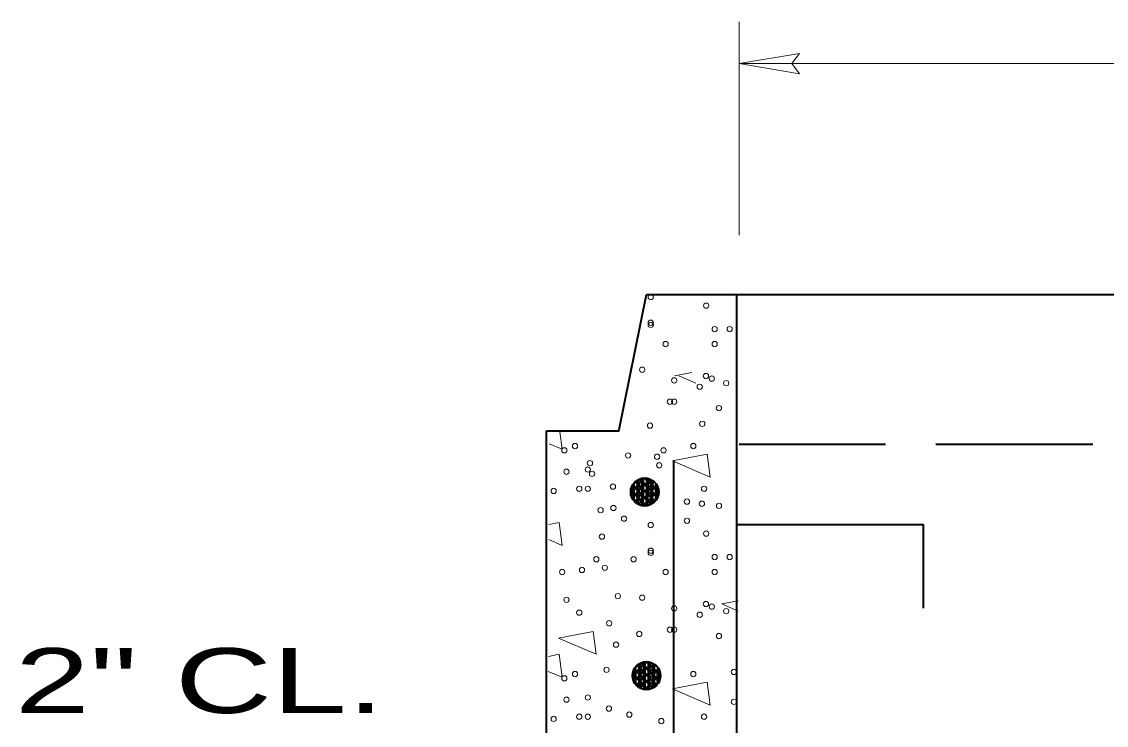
# Model space of a CAD drawing. Extents: x 5.1 to 20.2, y -16.7 to 4.3.
# Drawn here: x 9.029 to 11.185, y -3.824 to -2.427 of the extents above; entities that cross this region are included whole.
import ezdxf
from ezdxf.enums import TextEntityAlignment as Align

# ---------------------------------------------------------------- set-up
doc = ezdxf.new("R2010")
doc.units = 0
doc.header["$LTSCALE"] = 0.052
doc.linetypes.add('LONG_DASHED', pattern=[7.5, 6, -1.5])
for name, color, linetype, lineweight in [('1', 7, 'Continuous', 35), ('10', 7, 'Continuous', 13), ('13', 7, 'Continuous', 25), ('6', 7, 'Continuous', 13)]:
    doc.layers.add(name, color=color, linetype=linetype, lineweight=lineweight)

msp = doc.modelspace()

# ---------------------------------------------------------------- linework, layer by layer
at = {"layer": '1'}
for p, q in [((10.21608, -3.23967), (10.27058, -2.96833)), ((10.27058, -2.96833), (13.67525, -2.96833)), ((10.45017, -4.44358), (10.45017, -2.96833)), ((10.07242, -3.23933), (10.21608, -3.23933)), ((10.07242, -4.73767), (10.07242, -3.23933)), ((10.32492, -4.35042), (10.32492, -3.298)), ((10.26408, -3.3365), (10.24317, -3.35725)), ((10.267, -3.35925), (10.24817, -3.34033)), ((10.26058, -3.35275), (10.24817, -3.34033)), ((10.25408, -3.34617), (10.24817, -3.34033)), ((10.26775, -3.35825), (10.24908, -3.33958)), ((10.26125, -3.35175), (10.24908, -3.33958)), ((10.25475, -3.34517), (10.24908, -3.33958)), ((10.26775, -3.33292), (10.24958, -3.35075)), ((10.25275, -3.35983), (10.25283, -3.33692)), ((10.25275, -3.35067), (10.25283, -3.33692)), ((10.25275, -3.36908), (10.25283, -3.3395)), ((10.25283, -3.34142), (10.25283, -3.33692)), ((10.25533, -3.35983), (10.25542, -3.33542)), ((10.25533, -3.36908), (10.25542, -3.3395)), ((10.25542, -3.35067), (10.25542, -3.33542)), ((10.25542, -3.34142), (10.25542, -3.33542)), ((10.27358, -3.35275), (10.25608, -3.33525)), ((10.26708, -3.34625), (10.25608, -3.33525)), ((10.26067, -3.33967), (10.25608, -3.33525)), ((10.26775, -3.33292), (10.25617, -3.34425)), ((10.27717, -3.3365), (10.25617, -3.35733)), ((10.27425, -3.35175), (10.25725, -3.33467)), ((10.26775, -3.34525), (10.25725, -3.33467)), ((10.26125, -3.33875), (10.25725, -3.33467)), ((10.28008, -3.35933), (10.25925, -3.33842)), ((10.28075, -3.35833), (10.25992, -3.33742)), ((10.26192, -3.35992), (10.262, -3.33333)), ((10.26192, -3.36908), (10.262, -3.3395)), ((10.262, -3.35067), (10.262, -3.33333)), ((10.262, -3.3415), (10.262, -3.33333)), ((10.2785, -3.33525), (10.26267, -3.35083)), ((10.2645, -3.36908), (10.26467, -3.33958)), ((10.26458, -3.35992), (10.26467, -3.33292)), ((10.26458, -3.35067), (10.26467, -3.33292)), ((10.26458, -3.3415), (10.26467, -3.33292)), ((10.28658, -3.35283), (10.26683, -3.33292)), ((10.28008, -3.34625), (10.26683, -3.33292)), ((10.27358, -3.33975), (10.26683, -3.33292)), ((10.26708, -3.33317), (10.26683, -3.33292)), ((10.28733, -3.35183), (10.26842, -3.33292)), ((10.28083, -3.34525), (10.26842, -3.33292)), ((10.27433, -3.33883), (10.26842, -3.33292)), ((10.28625, -3.34042), (10.26917, -3.35733)), ((10.27117, -3.35992), (10.27125, -3.33317)), ((10.27117, -3.35067), (10.27125, -3.33317)), ((10.27117, -3.36908), (10.27125, -3.33958)), ((10.27125, -3.3415), (10.27125, -3.33317)), ((10.29308, -3.35933), (10.27233, -3.33842)), ((10.29375, -3.35833), (10.27292, -3.33742)), ((10.27375, -3.35992), (10.27383, -3.33367)), ((10.27375, -3.36917), (10.27383, -3.33958)), ((10.27383, -3.35067), (10.27383, -3.33367)), ((10.27383, -3.3415), (10.27383, -3.33367)), ((10.28033, -3.36917), (10.28042, -3.33958)), ((10.28042, -3.35992), (10.28042, -3.33625)), ((10.28042, -3.35075), (10.28042, -3.33625)), ((10.28042, -3.3415), (10.28042, -3.33625)), ((10.283, -3.35992), (10.28308, -3.33775)), ((10.283, -3.35075), (10.28308, -3.33775)), ((10.283, -3.36917), (10.28308, -3.33958)), ((10.28308, -3.3415), (10.28308, -3.33775)), ((10.25758, -3.343), (10.2395, -3.361)), ((10.251, -3.3495), (10.2395, -3.361)), ((10.2445, -3.35592), (10.2395, -3.361)), ((10.2605, -3.37875), (10.23958, -3.35783)), ((10.254, -3.37233), (10.23958, -3.35783)), ((10.2475, -3.36575), (10.23958, -3.35783)), ((10.241, -3.35917), (10.23958, -3.35783)), ((10.25467, -3.37133), (10.23975, -3.35625)), ((10.24808, -3.36475), (10.23975, -3.35625)), ((10.24167, -3.35817), (10.23975, -3.35625)), ((10.26117, -3.37783), (10.24033, -3.35692)), ((10.2575, -3.35592), (10.24175, -3.37175)), ((10.26058, -3.36575), (10.24267, -3.34775)), ((10.25408, -3.35925), (10.24267, -3.34775)), ((10.24758, -3.35267), (10.24267, -3.34775)), ((10.26408, -3.3495), (10.24308, -3.37033)), ((10.26117, -3.36483), (10.24317, -3.34667)), ((10.25467, -3.35825), (10.24317, -3.34667)), ((10.24817, -3.35167), (10.24317, -3.34667)), ((10.2435, -3.369), (10.24358, -3.34608)), ((10.2435, -3.35983), (10.24358, -3.34608)), ((10.2435, -3.37508), (10.24358, -3.34867)), ((10.2435, -3.37508), (10.2435, -3.35792)), ((10.24358, -3.35058), (10.24358, -3.34608)), ((10.24608, -3.36908), (10.24617, -3.3425)), ((10.24608, -3.37825), (10.24617, -3.34867)), ((10.24608, -3.37875), (10.24617, -3.35792)), ((10.24617, -3.35983), (10.24617, -3.3425)), ((10.24617, -3.35058), (10.24617, -3.3425)), ((10.267, -3.37233), (10.24617, -3.35133)), ((10.26767, -3.37133), (10.24683, -3.35042)), ((10.27058, -3.343), (10.24958, -3.36383)), ((10.27058, -3.356), (10.24958, -3.37692)), ((10.25267, -3.37825), (10.25275, -3.34875)), ((10.2735, -3.37883), (10.25267, -3.35783)), ((10.25267, -3.38433), (10.25275, -3.35792)), ((10.2735, -3.36583), (10.25275, -3.34492)), ((10.27417, -3.37792), (10.25333, -3.35692)), ((10.27425, -3.36483), (10.25342, -3.34392)), ((10.25525, -3.38583), (10.25533, -3.35792)), ((10.25533, -3.37825), (10.25542, -3.34875)), ((10.27708, -3.34958), (10.25608, -3.37042)), ((10.28, -3.37233), (10.25925, -3.35133)), ((10.28075, -3.37142), (10.25983, -3.35042)), ((10.26183, -3.3875), (10.262, -3.358)), ((10.26192, -3.37833), (10.262, -3.34875)), ((10.2835, -3.356), (10.26258, -3.37692)), ((10.28358, -3.34308), (10.26267, -3.36392)), ((10.2645, -3.37833), (10.26458, -3.34875)), ((10.2645, -3.3875), (10.26458, -3.358)), ((10.28658, -3.36583), (10.26575, -3.34492)), ((10.2865, -3.37883), (10.26575, -3.35792)), ((10.28725, -3.37792), (10.26633, -3.357)), ((10.28725, -3.36483), (10.26642, -3.34392)), ((10.29008, -3.34958), (10.26917, -3.37042)), ((10.27108, -3.37833), (10.27117, -3.34875)), ((10.27108, -3.38758), (10.27117, -3.358)), ((10.29267, -3.372), (10.27225, -3.35142)), ((10.29317, -3.37083), (10.27292, -3.3505)), ((10.27367, -3.38758), (10.27375, -3.358)), ((10.27375, -3.37833), (10.27383, -3.34875)), ((10.29192, -3.34775), (10.27567, -3.36392)), ((10.29492, -3.35775), (10.27567, -3.377)), ((10.29267, -3.372), (10.27867, -3.35792)), ((10.295, -3.36125), (10.27875, -3.345)), ((10.295, -3.35967), (10.27942, -3.344)), ((10.29317, -3.37083), (10.27942, -3.357)), ((10.28033, -3.37833), (10.28042, -3.34883)), ((10.28033, -3.38525), (10.28042, -3.358)), ((10.29492, -3.35775), (10.28217, -3.3705)), ((10.28292, -3.37833), (10.283, -3.34883)), ((10.28292, -3.38367), (10.283, -3.358)), ((10.295, -3.36125), (10.28525, -3.35142)), ((10.295, -3.35967), (10.28592, -3.3505)), ((10.2895, -3.37733), (10.28958, -3.34883)), ((10.2895, -3.37733), (10.28958, -3.35808)), ((10.28958, -3.36917), (10.28967, -3.34417)), ((10.28958, -3.36), (10.28967, -3.34417)), ((10.28958, -3.35075), (10.28967, -3.34417)), ((10.29217, -3.36917), (10.29225, -3.34842)), ((10.29217, -3.36), (10.29225, -3.34842)), ((10.29217, -3.37317), (10.29225, -3.34883)), ((10.29217, -3.37317), (10.29217, -3.35808)), ((10.29225, -3.35075), (10.29225, -3.34842)), ((10.25675, -3.38642), (10.24142, -3.371)), ((10.25458, -3.38433), (10.24142, -3.371)), ((10.24808, -3.37783), (10.24142, -3.371)), ((10.24167, -3.37125), (10.24142, -3.371)), ((10.251, -3.3625), (10.24175, -3.37175)), ((10.24442, -3.369), (10.24175, -3.37175)), ((10.25367, -3.385), (10.24283, -3.37408)), ((10.25367, -3.385), (10.24283, -3.37408)), ((10.2475, -3.37875), (10.24283, -3.37408)), ((10.2435, -3.37508), (10.2435, -3.36708)), ((10.24608, -3.37875), (10.24608, -3.36717)), ((10.25367, -3.385), (10.24608, -3.37742)), ((10.26692, -3.38533), (10.24617, -3.36433)), ((10.25675, -3.38642), (10.24675, -3.37642)), ((10.264, -3.3625), (10.24683, -3.37958)), ((10.26767, -3.38442), (10.24683, -3.36333)), ((10.2575, -3.369), (10.24683, -3.37958)), ((10.25092, -3.3755), (10.24683, -3.37958)), ((10.25267, -3.38433), (10.25275, -3.36717)), ((10.27, -3.38842), (10.25267, -3.37092)), ((10.25675, -3.38642), (10.25325, -3.383)), ((10.27142, -3.38817), (10.25333, -3.36992)), ((10.2705, -3.36908), (10.25417, -3.38525)), ((10.264, -3.37558), (10.25417, -3.38525)), ((10.25742, -3.38208), (10.25417, -3.38525)), ((10.25525, -3.38583), (10.25533, -3.36717)), ((10.27708, -3.3625), (10.25608, -3.38342)), ((10.28, -3.38533), (10.25917, -3.36442)), ((10.27, -3.38842), (10.25917, -3.37742)), ((10.27142, -3.38817), (10.25975, -3.37642)), ((10.28067, -3.38442), (10.25983, -3.36342)), ((10.26183, -3.388), (10.26192, -3.36717)), ((10.2835, -3.36908), (10.26417, -3.38833)), ((10.277, -3.37558), (10.26417, -3.38833)), ((10.2705, -3.38208), (10.26417, -3.38833)), ((10.2645, -3.38833), (10.26458, -3.36717)), ((10.28008, -3.38542), (10.26567, -3.37092)), ((10.28108, -3.38483), (10.26633, -3.36992)), ((10.29008, -3.36258), (10.26908, -3.3835)), ((10.27108, -3.38825), (10.27117, -3.36717)), ((10.2875, -3.37983), (10.27225, -3.36442)), ((10.28825, -3.37892), (10.27283, -3.36342)), ((10.27367, -3.38775), (10.27375, -3.36725)), ((10.28033, -3.38525), (10.28033, -3.36725)), ((10.29183, -3.37383), (10.28033, -3.38533)), ((10.29, -3.37567), (10.28033, -3.38533)), ((10.28342, -3.38217), (10.28033, -3.38533)), ((10.29183, -3.37383), (10.28217, -3.3835)), ((10.28292, -3.38367), (10.283, -3.36725)), ((10.29183, -3.37383), (10.28867, -3.377)), ((10.2895, -3.37733), (10.28958, -3.36725)), ((10.29217, -3.37317), (10.29217, -3.36725)), ((10.25367, -3.385), (10.25258, -3.38392)), ((10.2675, -3.70133), (10.24658, -3.72208)), ((10.27042, -3.72408), (10.25158, -3.70517)), ((10.264, -3.71758), (10.25158, -3.70517)), ((10.2575, -3.711), (10.25158, -3.70517)), ((10.27117, -3.72308), (10.2525, -3.70442)), ((10.26467, -3.71658), (10.2525, -3.70442)), ((10.25817, -3.71), (10.2525, -3.70442)), ((10.27117, -3.69775), (10.253, -3.71558)), ((10.25617, -3.72467), (10.25625, -3.70175)), ((10.25617, -3.7155), (10.25625, -3.70175)), ((10.25617, -3.73392), (10.25625, -3.70433)), ((10.25625, -3.70625), (10.25625, -3.70175)), ((10.25875, -3.72467), (10.25883, -3.70025)), ((10.25875, -3.73392), (10.25883, -3.70433)), ((10.25883, -3.7155), (10.25883, -3.70025)), ((10.25883, -3.70625), (10.25883, -3.70025)), ((10.277, -3.71758), (10.2595, -3.70008)), ((10.2705, -3.71108), (10.2595, -3.70008)), ((10.26408, -3.7045), (10.2595, -3.70008)), ((10.27117, -3.69775), (10.25958, -3.70908)), ((10.28058, -3.70133), (10.25958, -3.72217)), ((10.27767, -3.71658), (10.26067, -3.6995)), ((10.27117, -3.71008), (10.26067, -3.6995)), ((10.26467, -3.70358), (10.26067, -3.6995)), ((10.2835, -3.72417), (10.26267, -3.70325)), ((10.28417, -3.72317), (10.26333, -3.70225)), ((10.26533, -3.72475), (10.26542, -3.69817)), ((10.26533, -3.73392), (10.26542, -3.70433)), ((10.26542, -3.7155), (10.26542, -3.69817)), ((10.26542, -3.70633), (10.26542, -3.69817)), ((10.28192, -3.70008), (10.26608, -3.71567)), ((10.26792, -3.73392), (10.26808, -3.70442)), ((10.268, -3.72475), (10.26808, -3.69775)), ((10.268, -3.7155), (10.26808, -3.69775)), ((10.268, -3.70633), (10.26808, -3.69775)), ((10.29, -3.71767), (10.27025, -3.69775)), ((10.2835, -3.71108), (10.27025, -3.69775)), ((10.277, -3.70458), (10.27025, -3.69775)), ((10.2705, -3.698), (10.27025, -3.69775)), ((10.29075, -3.71667), (10.27183, -3.69775)), ((10.28425, -3.71008), (10.27183, -3.69775)), ((10.27775, -3.70367), (10.27183, -3.69775)), ((10.28967, -3.70525), (10.27258, -3.72217)), ((10.27458, -3.72475), (10.27467, -3.698)), ((10.27458, -3.7155), (10.27467, -3.698)), ((10.27458, -3.73392), (10.27467, -3.70442)), ((10.27467, -3.70633), (10.27467, -3.698)), ((10.2965, -3.72417), (10.27575, -3.70325)), ((10.29717, -3.72317), (10.27633, -3.70225)), ((10.27717, -3.72475), (10.27725, -3.6985)), ((10.27717, -3.734), (10.27725, -3.70442)), ((10.27725, -3.7155), (10.27725, -3.6985)), ((10.27725, -3.70633), (10.27725, -3.6985)), ((10.28375, -3.734), (10.28383, -3.70442)), ((10.28383, -3.72475), (10.28383, -3.70108)), ((10.28383, -3.71558), (10.28383, -3.70108)), ((10.28383, -3.70633), (10.28383, -3.70108)), ((10.28642, -3.72475), (10.2865, -3.70258)), ((10.28642, -3.71558), (10.2865, -3.70258)), ((10.28642, -3.734), (10.2865, -3.70442)), ((10.2865, -3.70633), (10.2865, -3.70258)), ((10.261, -3.70783), (10.24292, -3.72583)), ((10.25442, -3.71433), (10.24292, -3.72583)), ((10.24792, -3.72075), (10.24292, -3.72583)), ((10.26392, -3.74358), (10.243, -3.72267)), ((10.25742, -3.73717), (10.243, -3.72267)), ((10.25092, -3.73058), (10.243, -3.72267)), ((10.24442, -3.724), (10.243, -3.72267)), ((10.25808, -3.73617), (10.24317, -3.72108)), ((10.2515, -3.72958), (10.24317, -3.72108)), ((10.24508, -3.723), (10.24317, -3.72108)), ((10.26458, -3.74267), (10.24375, -3.72175)), ((10.26092, -3.72075), (10.24517, -3.73658)), ((10.25442, -3.72733), (10.24517, -3.73658)), ((10.264, -3.73058), (10.24608, -3.71258)), ((10.2575, -3.72408), (10.24608, -3.71258)), ((10.251, -3.7175), (10.24608, -3.71258)), ((10.2675, -3.71433), (10.2465, -3.73517)), ((10.26458, -3.72967), (10.24658, -3.7115)), ((10.25808, -3.72308), (10.24658, -3.7115)), ((10.25158, -3.7165), (10.24658, -3.7115)), ((10.24692, -3.73383), (10.247, -3.71092)), ((10.24692, -3.72467), (10.247, -3.71092)), ((10.24692, -3.73992), (10.247, -3.7135)), ((10.24692, -3.73992), (10.24692, -3.72275)), ((10.247, -3.71542), (10.247, -3.71092)), ((10.2495, -3.73392), (10.24958, -3.70733)), ((10.2495, -3.74308), (10.24958, -3.7135)), ((10.2495, -3.74358), (10.24958, -3.72275)), ((10.24958, -3.72467), (10.24958, -3.70733)), ((10.24958, -3.71542), (10.24958, -3.70733)), ((10.27042, -3.73717), (10.24958, -3.71617)), ((10.27108, -3.73617), (10.25025, -3.71525)), ((10.26742, -3.72733), (10.25025, -3.74442)), ((10.27108, -3.74925), (10.25025, -3.72817)), ((10.274, -3.70783), (10.253, -3.72867)), ((10.274, -3.72083), (10.253, -3.74175)), ((10.25608, -3.74308), (10.25617, -3.71358)), ((10.27692, -3.74367), (10.25608, -3.72267)), ((10.25608, -3.74917), (10.25617, -3.72275)), ((10.27692, -3.73067), (10.25617, -3.70975)), ((10.27758, -3.74275), (10.25675, -3.72175)), ((10.27767, -3.72967), (10.25683, -3.70875)), ((10.25867, -3.75067), (10.25875, -3.72275)), ((10.25875, -3.74308), (10.25883, -3.71358)), ((10.2805, -3.71442), (10.2595, -3.73525)), ((10.2805, -3.72733), (10.2595, -3.74825)), ((10.28342, -3.73717), (10.26267, -3.71617)), ((10.28417, -3.73625), (10.26325, -3.71525)), ((10.28408, -3.74925), (10.26325, -3.72825)), ((10.26525, -3.75233), (10.26542, -3.72283)), ((10.26533, -3.74317), (10.26542, -3.71358)), ((10.28692, -3.72083), (10.266, -3.74175)), ((10.287, -3.70792), (10.26608, -3.72875)), ((10.26792, -3.74317), (10.268, -3.71358)), ((10.26792, -3.75233), (10.268, -3.72283)), ((10.29, -3.73067), (10.26917, -3.70975)), ((10.28992, -3.74367), (10.26917, -3.72275)), ((10.29067, -3.74275), (10.26975, -3.72183)), ((10.29067, -3.72967), (10.26983, -3.70875)), ((10.2935, -3.72742), (10.2725, -3.74833)), ((10.2935, -3.71442), (10.27258, -3.73525)), ((10.2745, -3.74317), (10.27458, -3.71358)), ((10.2745, -3.75242), (10.27458, -3.72283)), ((10.29608, -3.73683), (10.27567, -3.71625)), ((10.29167, -3.74375), (10.27625, -3.72825)), ((10.29658, -3.73567), (10.27633, -3.71533)), ((10.27708, -3.75242), (10.27717, -3.72283)), ((10.27717, -3.74317), (10.27725, -3.71358)), ((10.29533, -3.71258), (10.27908, -3.72875)), ((10.29833, -3.72258), (10.27908, -3.74183)), ((10.29608, -3.73683), (10.28208, -3.72275)), ((10.29842, -3.72608), (10.28217, -3.70983)), ((10.29842, -3.7245), (10.28283, -3.70883)), ((10.29658, -3.73567), (10.28283, -3.72183)), ((10.28375, -3.74317), (10.28383, -3.71367)), ((10.28375, -3.75008), (10.28383, -3.72283)), ((10.29833, -3.72258), (10.28558, -3.73533)), ((10.28633, -3.74317), (10.28642, -3.71367)), ((10.28633, -3.7485), (10.28642, -3.72283)), ((10.29842, -3.72608), (10.28867, -3.71625)), ((10.29842, -3.7245), (10.28933, -3.71533)), ((10.29292, -3.74217), (10.293, -3.71367)), ((10.29292, -3.74217), (10.293, -3.72292)), ((10.293, -3.734), (10.29308, -3.709)), ((10.293, -3.72483), (10.29308, -3.709)), ((10.293, -3.71558), (10.29308, -3.709)), ((10.29558, -3.734), (10.29567, -3.71325)), ((10.29558, -3.72483), (10.29567, -3.71325)), ((10.29558, -3.738), (10.29567, -3.71367)), ((10.29558, -3.738), (10.29558, -3.72292)), ((10.29567, -3.71558), (10.29567, -3.71325)), ((10.26017, -3.75125), (10.24483, -3.73583)), ((10.258, -3.74917), (10.24483, -3.73583)), ((10.2515, -3.74267), (10.24483, -3.73583)), ((10.24508, -3.73608), (10.24483, -3.73583)), ((10.24783, -3.73383), (10.24517, -3.73658)), ((10.25708, -3.74983), (10.24625, -3.73892)), ((10.25708, -3.74983), (10.24625, -3.73892)), ((10.25092, -3.74358), (10.24625, -3.73892)), ((10.24692, -3.73992), (10.24692, -3.73192)), ((10.2495, -3.74358), (10.2495, -3.732)), ((10.25708, -3.74983), (10.2495, -3.74225)), ((10.27033, -3.75017), (10.24958, -3.72917)), ((10.26017, -3.75125), (10.25017, -3.74125)), ((10.26092, -3.73383), (10.25025, -3.74442)), ((10.25433, -3.74033), (10.25025, -3.74442)), ((10.25708, -3.74983), (10.256, -3.74875)), ((10.25608, -3.74917), (10.25617, -3.732)), ((10.27342, -3.75325), (10.25608, -3.73575)), ((10.26017, -3.75125), (10.25667, -3.74783)), ((10.27483, -3.753), (10.25675, -3.73475)), ((10.27392, -3.73392), (10.25758, -3.75008)), ((10.26742, -3.74042), (10.25758, -3.75008)), ((10.26083, -3.74692), (10.25758, -3.75008)), ((10.25867, -3.75067), (10.25875, -3.732)), ((10.28342, -3.75017), (10.26258, -3.72925)), ((10.27342, -3.75325), (10.26258, -3.74225)), ((10.27483, -3.753), (10.26317, -3.74125)), ((10.26525, -3.75283), (10.26533, -3.732)), ((10.28692, -3.73392), (10.26758, -3.75317)), ((10.28042, -3.74042), (10.26758, -3.75317)), ((10.27392, -3.74692), (10.26758, -3.75317)), ((10.26792, -3.75317), (10.268, -3.732)), ((10.2835, -3.75025), (10.26908, -3.73575)), ((10.2845, -3.74967), (10.26975, -3.73475)), ((10.2745, -3.75308), (10.27458, -3.732)), ((10.29092, -3.74467), (10.27567, -3.72925)), ((10.27708, -3.75258), (10.27717, -3.73208)), ((10.28375, -3.75008), (10.28375, -3.73208)), ((10.29525, -3.73867), (10.28375, -3.75017)), ((10.29342, -3.7405), (10.28375, -3.75017)), ((10.28683, -3.747), (10.28375, -3.75017)), ((10.29525, -3.73867), (10.28558, -3.74833)), ((10.28633, -3.7485), (10.28642, -3.73208)), ((10.29525, -3.73867), (10.29208, -3.74183)), ((10.29292, -3.74217), (10.293, -3.73208)), ((10.29558, -3.738), (10.29558, -3.73208))]:
    msp.add_line(p, q, dxfattribs=at)
at = {"layer": '1', "linetype": 'LONG_DASHED'}
msp.add_line((11.98158, -3.26633), (10.45483, -3.26633), dxfattribs=at)
at = {"layer": '1'}
msp.add_lwpolyline([(10.45017, -3.425), (10.82075, -3.425), (10.82075, -3.59158)], dxfattribs=at)
for centre in [(10.26727, -3.36068), (10.27069, -3.72551)]:
    msp.add_circle(centre, 0.02789, dxfattribs=at)
at = {"layer": '10'}
for p, q in [((10.45475, -2.85092), (10.45475, -2.42667)), ((10.57475, -2.49), (10.45475, -2.51)), ((10.57475, -2.49), (10.55975, -2.51)), ((10.45475, -2.51), (13.44833, -2.51)), ((10.57475, -2.53), (10.45475, -2.51)), ((10.57475, -2.53), (10.55975, -2.51))]:
    msp.add_line(p, q, dxfattribs=at)
at = {"layer": '6'}
for p, q in [((10.32667, -3.13025), (10.36067, -3.12358)), ((10.36892, -3.14483), (10.335, -3.13025)), ((10.42025, -3.583), (10.45283, -3.57667)), ((10.45275, -3.597), (10.42025, -3.583))]:
    msp.add_line(p, q, dxfattribs=at)
for points in [[(10.09858, -3.24133), (10.10308, -3.27583), (10.07708, -3.26467)], [(10.07658, -3.42517), (10.09708, -3.42108), (10.10308, -3.46667), (10.07642, -3.45525)], [(10.07575, -3.68725), (10.09708, -3.683), (10.10308, -3.72858), (10.07567, -3.71683)]]:
    msp.add_lwpolyline(points, dxfattribs=at)
for points in [[(10.32275, -3.29892), (10.39167, -3.28542), (10.39767, -3.331)], [(10.096, -3.65092), (10.16492, -3.63742), (10.17092, -3.683)], [(10.32275, -3.75167), (10.39167, -3.73817), (10.39767, -3.78375)]]:
    msp.add_lwpolyline(points, close=True, dxfattribs=at)
for centre in [(10.27917, -2.97358), (10.38942, -2.99058), (10.27917, -3.0245), (10.27917, -3.02875), (10.40633, -3.03717), (10.43608, -3.03717), (10.30883, -3.06692), (10.40633, -3.06692), (10.26217, -3.11775), (10.38892, -3.13033), (10.32575, -3.139), (10.37667, -3.15167), (10.40067, -3.13542), (10.42908, -3.1445), (10.31733, -3.18142), (10.32575, -3.18142), (10.41483, -3.19408), (10.27778, -3.22875), (10.38162, -3.22533), (10.1075, -3.27792), (10.12875, -3.26942), (10.30458, -3.27792), (10.36392, -3.26942), (10.23427, -3.28812), (10.29183, -3.29067), (10.11175, -3.32033), (10.15417, -3.31608), (10.15842, -3.30333), (10.29608, -3.30758), (10.16267, -3.32458), (10.08633, -3.3585), (10.13717, -3.35425), (10.15417, -3.35425), (10.20418, -3.35), (10.38517, -3.35425), (10.35125, -3.37967), (10.38092, -3.38392), (10.41486, -3.38817), (10.17958, -3.39667), (10.20508, -3.39242), (10.22625, -3.41358), (10.27917, -3.42633), (10.35125, -3.41783), (10.1822, -3.44925), (10.38942, -3.44333), (10.17117, -3.49417), (10.24525, -3.49417), (10.27917, -3.47725), (10.27917, -3.4815), (10.40633, -3.48992), (10.43608, -3.48992), (10.14262, -3.51542), (10.18808, -3.51117), (10.10325, -3.51967), (10.30883, -3.51967), (10.40633, -3.51967), (10.11175, -3.57475), (10.2138, -3.5675), (10.26217, -3.5705), (10.38892, -3.58308), (10.13717, -3.60025), (10.32575, -3.59175), (10.37667, -3.60442), (10.40067, -3.58817), (10.42908, -3.59725), (10.19658, -3.62142), (10.25648, -3.64249), (10.31733, -3.63417), (10.32575, -3.63417), (10.41483, -3.64683), (10.21034, -3.66383), (10.1075, -3.73067), (10.12875, -3.72217), (10.19145, -3.71383), (10.36392, -3.72217), (10.4445, -3.71792), (10.11175, -3.77308), (10.15417, -3.76883), (10.19623, -3.79085), (10.4445, -3.77733), (10.08633, -3.81125), (10.13717, -3.807), (10.15417, -3.807), (10.23675, -3.80275), (10.30033, -3.8155), (10.38517, -3.807)]:
    msp.add_circle(centre, 0.00525, dxfattribs=at)

# ---------------------------------------------------------------- texts
at = {"layer": '13', "width": 1.55}
msp.add_text('2" CL.', height=0.129, dxfattribs=at).set_placement((9.38275, -3.79975), align=Align.CENTER)

doc.saveas('drawing.dxf')
